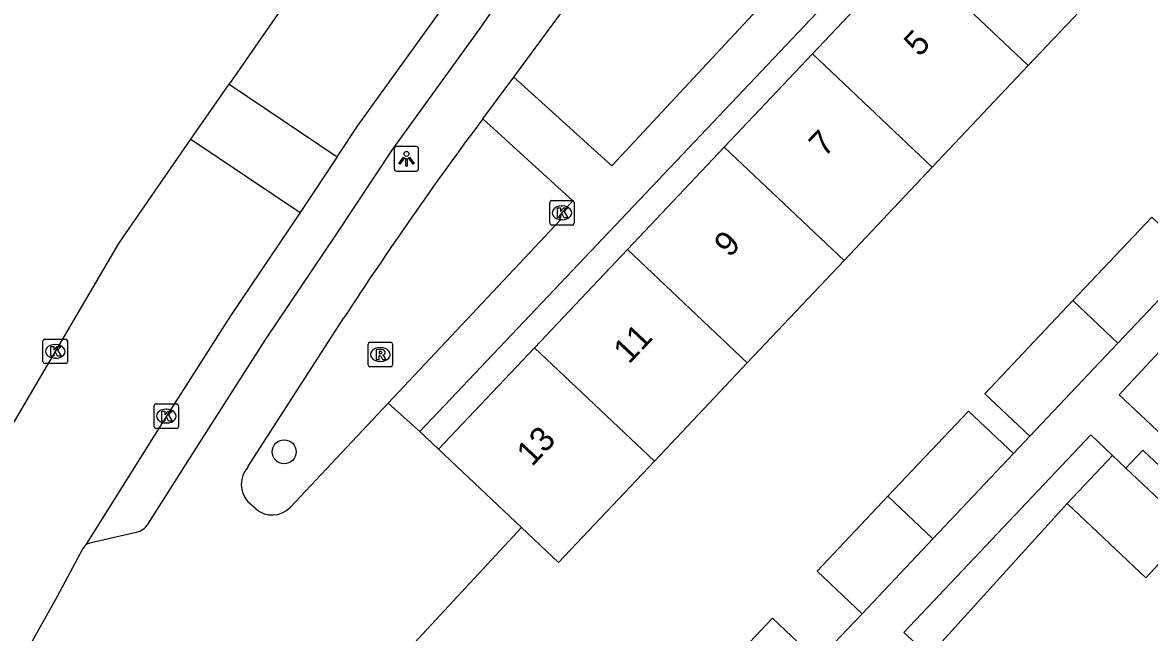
# Model space of a CAD drawing. Extents: x 159040 to 160094, y 381214 to 382518.
# Drawn here: x 159247.56 to 159293.61, y 381642.29 to 381667.19 of the extents above; entities that cross this region are included whole.
import ezdxf

# ---------------------------------------------------------------- set-up
doc = ezdxf.new("R2010")
doc.units = 0
for name, color, linetype in [('IMGEO_Boom', 7, 'Continuous'), ('IMGEO_Groenvoorziening', 7, 'Continuous'), ('IMGEO_Kolk', 7, 'Continuous'), ('IMGEO_Lichtpunt', 7, 'Continuous'), ('IMGEO_Pand', 7, 'Continuous'), ('IMGEO_Pand_nummerreeks', 7, 'Continuous'), ('IMGEO_Rijbaan_lokaal_open', 7, 'Continuous'), ('IMGEO_Rioolput', 7, 'Continuous'), ('IMGEO_Voetpad_open', 7, 'Continuous')]:
    doc.layers.add(name, color=color, linetype=linetype)

msp = doc.modelspace()

# ---------------------------------------------------------------- linework, layer by layer
at = {"layer": 'IMGEO_Boom'}
msp.add_circle((159258.251, 381649.666), 0.489, dxfattribs=at)
at = {"layer": 'IMGEO_Groenvoorziening'}
msp.add_lwpolyline([(159290.242, 381647.551), (159284.602, 381641.339)], dxfattribs=at)
at = {"layer": 'IMGEO_Kolk'}
for p, q in [((159269.173, 381659.924), (159270.025, 381659.924)), ((159269.098, 381658.998), (159269.098, 381659.85)), ((159269.586, 381659.704), (159269.611, 381659.704)), ((159270.099, 381659.85), (159270.099, 381658.998)), ((159269.609, 381659.144), (159269.584, 381659.144)), ((159270.025, 381658.924), (159269.173, 381658.924)), ((159248.395, 381653.339), (159248.395, 381654.191)), ((159248.47, 381654.265), (159249.322, 381654.265)), ((159248.883, 381654.045), (159248.908, 381654.045)), ((159249.396, 381654.191), (159249.396, 381653.339)), ((159248.906, 381653.485), (159248.881, 381653.485)), ((159249.322, 381653.265), (159248.47, 381653.265)), ((159253.009, 381651.622), (159253.861, 381651.622)), ((159252.934, 381650.696), (159252.934, 381651.548)), ((159253.422, 381651.402), (159253.447, 381651.402)), ((159253.935, 381651.548), (159253.935, 381650.696)), ((159253.445, 381650.842), (159253.42, 381650.842)), ((159253.861, 381650.622), (159253.009, 381650.622))]:
    msp.add_line(p, q, dxfattribs=at)
for points in [[(159269.173, 381659.924), (159270.025, 381659.924)], [(159269.098, 381658.998), (159269.098, 381659.85)], [(159269.419, 381659.624), (159269.542, 381659.624), (159269.542, 381659.473), (159269.672, 381659.624), (159269.836, 381659.624), (159269.69, 381659.473), (159269.843, 381659.224), (159269.691, 381659.224), (159269.606, 381659.388), (159269.542, 381659.321), (159269.542, 381659.224), (159269.419, 381659.224), (159269.419, 381659.624)], [(159270.099, 381659.85), (159270.099, 381658.998)], [(159270.025, 381658.924), (159269.173, 381658.924)], [(159248.395, 381653.339), (159248.395, 381654.191)], [(159248.47, 381654.265), (159249.322, 381654.265)], [(159248.716, 381653.965), (159248.839, 381653.965), (159248.839, 381653.814), (159248.969, 381653.965), (159249.133, 381653.965), (159248.987, 381653.814), (159249.14, 381653.565), (159248.988, 381653.565), (159248.903, 381653.729), (159248.839, 381653.662), (159248.839, 381653.565), (159248.716, 381653.565), (159248.716, 381653.965)], [(159249.396, 381654.191), (159249.396, 381653.339)], [(159249.322, 381653.265), (159248.47, 381653.265)], [(159253.009, 381651.622), (159253.861, 381651.622)], [(159252.934, 381650.696), (159252.934, 381651.548)], [(159253.255, 381651.322), (159253.378, 381651.322), (159253.378, 381651.171), (159253.508, 381651.322), (159253.672, 381651.322), (159253.526, 381651.171), (159253.679, 381650.922), (159253.527, 381650.922), (159253.442, 381651.086), (159253.378, 381651.019), (159253.378, 381650.922), (159253.255, 381650.922), (159253.255, 381651.322)], [(159253.935, 381651.548), (159253.935, 381650.696)], [(159253.861, 381650.622), (159253.009, 381650.622)]]:
    msp.add_lwpolyline(points, dxfattribs=at)
for centre, start, end in [((159269.175, 381659.848), 91.552, 178.448), ((159269.175, 381659.848), 91.552, 178.448), ((159270.023, 381659.848), 1.552, 88.448), ((159270.023, 381659.848), 1.552, 88.448), ((159269.175, 381659), 181.552, 268.448), ((159269.175, 381659), 181.552, 268.448), ((159270.023, 381659), 271.552, 358.448), ((159270.023, 381659), 271.552, 358.448), ((159248.472, 381654.189), 91.552, 178.448), ((159248.472, 381654.189), 91.552, 178.448), ((159249.32, 381654.189), 1.552, 88.448), ((159249.32, 381654.189), 1.552, 88.448), ((159248.472, 381653.341), 181.552, 268.448), ((159248.472, 381653.341), 181.552, 268.448), ((159249.32, 381653.341), 271.552, 358.448), ((159249.32, 381653.341), 271.552, 358.448), ((159253.011, 381651.546), 91.552, 178.448), ((159253.011, 381651.546), 91.552, 178.448), ((159253.859, 381651.546), 1.552, 88.448), ((159253.859, 381651.546), 1.552, 88.448), ((159253.011, 381650.698), 181.552, 268.448), ((159253.011, 381650.698), 181.552, 268.448), ((159253.859, 381650.698), 271.552, 358.448), ((159253.859, 381650.698), 271.552, 358.448)]:
    msp.add_arc(centre, 0.0765, start, end, dxfattribs=at)
for centre, major_axis, ratio, start_param, end_param in [((159269.585, 381659.424), (-0.387, 0.002), 0.722429, 4.712389, 7.853982), ((159269.61, 381659.424), (-0.39, 0.002), 0.717154, 1.570796, 4.712389), ((159248.882, 381653.765), (-0.387, 0.002), 0.722429, 4.712389, 7.853982), ((159248.907, 381653.765), (-0.39, 0.002), 0.717154, 1.570796, 4.712389), ((159253.421, 381651.122), (-0.387, 0.002), 0.722429, 4.712389, 7.853982), ((159253.446, 381651.122), (-0.39, 0.002), 0.717154, 1.570796, 4.712389)]:
    msp.add_ellipse(centre, major_axis=major_axis, ratio=ratio, start_param=start_param, end_param=end_param, dxfattribs=at)
at = {"layer": 'IMGEO_Lichtpunt'}
for p, q in [((159262.749, 381662.032), (159262.749, 381661.225)), ((159262.749, 381662.032), (159262.749, 381661.225)), ((159263.651, 381662.127), (159262.843, 381662.127)), ((159263.651, 381662.127), (159262.843, 381662.127)), ((159263.745, 381661.225), (159263.745, 381662.032)), ((159263.745, 381661.225), (159263.745, 381662.032)), ((159262.843, 381661.131), (159263.651, 381661.131)), ((159262.843, 381661.131), (159263.651, 381661.131))]:
    msp.add_line(p, q, dxfattribs=at)
for points in [[(159263.123, 381661.696), (159263.162, 381661.668), (159262.974, 381661.406), (159262.936, 381661.433), (159263.123, 381661.696)], [(159263.225, 381661.648), (159263.272, 381661.648), (159263.272, 381661.326), (159263.225, 381661.326), (159263.225, 381661.648)], [(159263.335, 381661.668), (159263.373, 381661.695), (159263.56, 381661.433), (159263.521, 381661.405), (159263.335, 381661.668)]]:
    msp.add_lwpolyline(points, dxfattribs=at)
msp.add_circle((159263.248, 381661.83), 0.0994, dxfattribs=at)
for centre, start, end in [((159262.843, 381662.032), 90, 180), ((159262.843, 381662.032), 90, 180), ((159263.651, 381662.032), 0, 90), ((159263.651, 381662.032), 0, 90), ((159262.843, 381661.225), 180, 270), ((159262.843, 381661.225), 180, 270), ((159263.651, 381661.225), 270, 0), ((159263.651, 381661.225), 270, 360)]:
    msp.add_arc(centre, 0.0946, start, end, dxfattribs=at)
at = {"layer": 'IMGEO_Pand'}
for points in [[(159283.762, 381670.065), (159279.836, 381665.917)], [(159283.762, 381670.065), (159288.655, 381665.436)], [(159292.562, 381669.565), (159288.655, 381665.436)], [(159279.836, 381665.917), (159276.233, 381662.107)], [(159284.73, 381661.287), (159279.836, 381665.917)], [(159288.655, 381665.436), (159284.73, 381661.287)], [(159276.233, 381662.107), (159272.277, 381657.926)], [(159281.126, 381657.478), (159276.233, 381662.107)], [(159284.73, 381661.287), (159281.126, 381657.478)], [(159295.537, 381657.507), (159293.698, 381659.247), (159290.481, 381655.846)], [(159272.277, 381657.926), (159268.483, 381653.917)], [(159272.277, 381657.926), (159277.17, 381653.297)], [(159281.126, 381657.478), (159277.17, 381653.297)], [(159292.32, 381654.107), (159295.537, 381657.507)], [(159288.716, 381650.298), (159286.877, 381652.037), (159290.481, 381655.846)], [(159290.481, 381655.846), (159292.32, 381654.107)], [(159268.483, 381653.917), (159264.562, 381649.772)], [(159268.483, 381653.917), (159273.376, 381649.288)], [(159292.32, 381654.107), (159288.716, 381650.298)], [(159277.17, 381653.297), (159273.376, 381649.288)], [(159282.921, 381647.856), (159286.207, 381651.329), (159288.046, 381649.59)], [(159267.948, 381646.568), (159264.562, 381649.772)], [(159288.046, 381649.59), (159284.76, 381646.116)], [(159292.1, 381649.515), (159290.242, 381647.551)], [(159292.641, 381649.003), (159292.1, 381649.515)], [(159273.376, 381649.288), (159269.455, 381645.143), (159267.948, 381646.568)], [(159294.273, 381647.46), (159292.641, 381649.003)], [(159282.921, 381647.856), (159280.023, 381644.793), (159281.863, 381643.054)], [(159284.76, 381646.116), (159282.921, 381647.856)], [(159295.298, 381646.49), (159293.452, 381644.514), (159290.242, 381647.551)], [(159281.863, 381643.054), (159284.76, 381646.116)], [(159280.041, 381641.128), (159278.201, 381642.868), (159275.174, 381639.668), (159277.013, 381637.928)]]:
    msp.add_lwpolyline(points, dxfattribs=at)
at = {"layer": 'IMGEO_Rijbaan_lokaal_open'}
for points in [[(159273.747, 381687.9), (159272.115, 381686.142), (159267.603, 381680.595), (159260.442, 381671.089), (159255.999, 381664.677)], [(159260.413, 381661.709), (159261.276, 381663.007), (159264.834, 381667.935), (159266.302, 381670.07), (159269.115, 381673.75), (159272.579, 381678.156), (159273.822, 381679.732)], [(159254.442, 381662.43), (159255.999, 381664.677)], [(159255.999, 381664.677), (159260.413, 381661.709)], [(159246.484, 381649.656), (159251.495, 381658.176), (159254.442, 381662.43)], [(159254.442, 381662.43), (159258.898, 381659.432)], [(159260.413, 381661.709), (159258.898, 381659.432)], [(159258.898, 381659.432), (159256.057, 381655.213), (159253.409, 381651.085), (159250.159, 381645.899)], [(159250.159, 381645.899), (159250.029, 381645.71), (159248.972, 381643.759), (159246, 381638.47), (159244.937, 381636.725), (159244.844, 381636.563)]]:
    msp.add_lwpolyline(points, dxfattribs=at)
at = {"layer": 'IMGEO_Rioolput'}
for p, q in [((159261.677, 381653.21), (159261.677, 381654.062)), ((159261.752, 381654.136), (159262.604, 381654.136)), ((159262.165, 381653.916), (159262.19, 381653.916)), ((159262.678, 381654.062), (159262.678, 381653.21)), ((159262.604, 381653.136), (159261.752, 381653.136)), ((159262.188, 381653.356), (159262.163, 381653.356))]:
    msp.add_line(p, q, dxfattribs=at)
for points in [[(159261.677, 381653.21), (159261.677, 381654.062)], [(159261.752, 381654.136), (159262.604, 381654.136)], [(159262.678, 381654.062), (159262.678, 381653.21)], [(159262.266, 381653.834), (159262.014, 381653.836), (159262.014, 381653.436)], [(159262.014, 381653.436), (159262.138, 381653.436), (159262.138, 381653.598), (159262.149, 381653.598)], [(159262.192, 381653.755), (159262.138, 381653.755), (159262.138, 381653.674)], [(159262.138, 381653.674), (159262.19, 381653.674)], [(159262.196, 381653.569), (159262.267, 381653.436), (159262.407, 381653.436), (159262.342, 381653.562)], [(159262.604, 381653.136), (159261.752, 381653.136)]]:
    msp.add_lwpolyline(points, dxfattribs=at)
for centre, radius, start, end in [((159261.754, 381654.06), 0.0765, 91.552, 178.448), ((159261.754, 381654.06), 0.0765, 91.552, 178.448), ((159262.602, 381654.06), 0.0765, 1.552, 88.448), ((159262.602, 381654.06), 0.0765, 1.552, 88.448), ((159262.148, 381653.545), 0.0533, 26.0293, 88.6989), ((159262.174, 381653.863), 0.19, 274.7715, 282.9687), ((159262.198, 381653.659), 0.0964, 77.0061, 93.1865), ((159262.212, 381653.716), 0.0378, 276.6634, 79.6772), ((159262.265, 381653.724), 0.109, 350.3612, 89.416), ((159262.263, 381653.724), 0.112, 277.5842, 350.9817), ((159262.247, 381653.509), 0.108, 29.5134, 73.7905), ((159261.754, 381653.212), 0.0765, 181.552, 268.448), ((159261.754, 381653.212), 0.0765, 181.552, 268.448), ((159262.602, 381653.212), 0.0765, 271.552, 358.448), ((159262.602, 381653.212), 0.0765, 271.552, 358.448)]:
    msp.add_arc(centre, radius, start, end, dxfattribs=at)
for centre, major_axis, ratio, start_param, end_param in [((159262.164, 381653.636), (-0.387, 0.002), 0.722429, 4.712389, 7.853982), ((159262.189, 381653.636), (-0.39, 0.002), 0.717154, 1.570796, 4.712389)]:
    msp.add_ellipse(centre, major_axis=major_axis, ratio=ratio, start_param=start_param, end_param=end_param, dxfattribs=at)
at = {"layer": 'IMGEO_Voetpad_open'}
for points in [[(159263.796, 381650.493), (159290.97, 381679.148)], [(159252.698, 381646.729), (159254.866, 381650.157), (159257.501, 381654.264), (159260.388, 381658.551), (159262.696, 381662.023), (159266.246, 381666.94), (159267.701, 381669.055), (159270.48, 381672.691), (159275.088, 381678.55)], [(159267.635, 381664.961), (159271.102, 381669.693), (159276.049, 381676.12)], [(159267.635, 381664.961), (159271.637, 381661.344), (159281.099, 381671.509), (159276.049, 381676.12)], [(159266.363, 381663.258), (159267.635, 381664.961)], [(159266.363, 381663.258), (159270.045, 381659.915), (159269.597, 381659.424), (159269.46, 381659.264), (159269.556, 381659.157), (159262.498, 381651.654)], [(159301.759, 381659.594), (159300.531, 381660.74), (159292.369, 381651.992), (159295.691, 381648.875), (159296.49, 381649.727)], [(159256.771, 381649.044), (159260.694, 381655.13)], [(159262.498, 381651.654), (159258.488, 381647.39)], [(159263.796, 381650.493), (159262.498, 381651.654)], [(159264.562, 381649.772), (159263.796, 381650.493)], [(159292.1, 381649.515), (159291.208, 381650.359), (159283.566, 381642.28), (159284.602, 381641.339)], [(159288.046, 381649.59), (159288.716, 381650.298)], [(159294.273, 381647.46), (159294.968, 381648.194), (159293.33, 381649.731), (159292.641, 381649.003)], [(159257.102, 381647.324), (159256.77, 381647.62)], [(159267.948, 381646.568), (159262.336, 381640.53)], [(159250.159, 381645.899), (159250.359, 381645.96), (159252.198, 381646.376)], [(159280.041, 381641.128), (159280.967, 381642.107), (159281.863, 381643.054)]]:
    msp.add_lwpolyline(points, dxfattribs=at)
for centre, radius, start, end in [((159385.903, 381573.842), 149.282, 143.20349, 147.00762), ((159257.568, 381648.331), 1.069, 138.2141, 221.7055), ((159257.76, 381648.1), 1.017, 229.7234, 315.7292), ((159252.02, 381647.159), 0.803, 282.8117, 327.6325)]:
    msp.add_arc(centre, radius, start, end, dxfattribs=at)

# ---------------------------------------------------------------- texts
at = {"layer": 'IMGEO_Pand_nummerreeks'}
for s, p in [('5', (159284.203, 381665.758)), ('7', (159280.326, 381661.66)), ('9', (159276.448, 381657.562)), ('11', (159272.333, 381653.213)), ('13', (159268.378, 381649.033))]:
    msp.add_text(s, height=1, rotation=46.5863, dxfattribs=at).set_placement(p)

doc.saveas('drawing.dxf')
